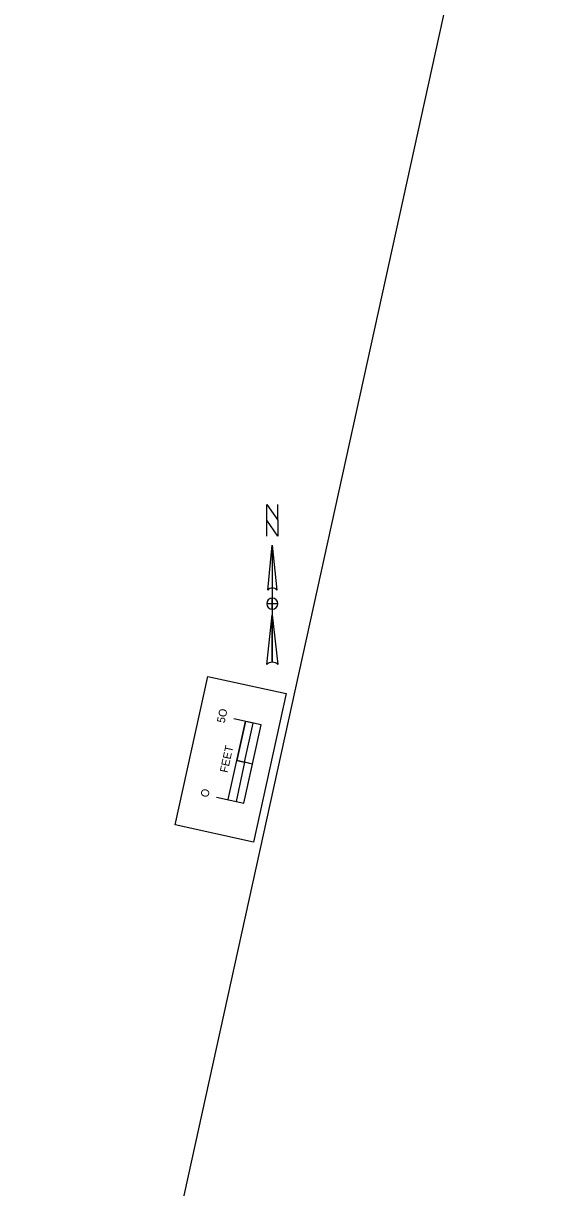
# Model space of a CAD drawing. Extents: x 14104283 to 14120882, y 8635219 to 8671666.
# Drawn here: x 14108486 to 14108813, y 8640168 to 8640895 of the extents above; entities that cross this region are included whole.
import ezdxf

# ---------------------------------------------------------------- set-up
doc = ezdxf.new("R2010")
doc.units = 0
for name, color, linetype in [('dsnCellsNorthArrow', 7, 'Continuous'), ('dsnCellsScaleBlock', 7, 'Continuous'), ('dsnNonPlotable', 7, 'Continuous')]:
    doc.layers.add(name, color=color, linetype=linetype)

msp = doc.modelspace()

# ---------------------------------------------------------------- linework, layer by layer
at = {"layer": 'dsnCellsNorthArrow'}
for p, q in [((14108641.86, 8640569.29), (14108644.67, 8640541.12)), ((14108641.86, 8640569.29), (14108641.86, 8640496.05)), ((14108639.04, 8640541.12), (14108639.04, 8640541.12)), ((14108639.15, 8640541.38), (14108639.67, 8640541.97)), ((14108641.86, 8640529.15), (14108641.86, 8640529.15)), ((14108638.34, 8640494.64), (14108641.86, 8640525.63))]:
    msp.add_line(p, q, dxfattribs=at)
msp.add_lwpolyline([(14108645.38, 8640574.93), (14108638.34, 8640584.79), (14108638.34, 8640594.65), (14108645.38, 8640584.79)], close=True, dxfattribs=at)
for points in [[(14108638.34, 8640574.93), (14108638.34, 8640594.65), (14108645.38, 8640584.79), (14108645.38, 8640594.65)], [(14108639.04, 8640541.12), (14108641.86, 8640569.29), (14108641.86, 8640542.53)], [(14108645.38, 8640532.67), (14108641.86, 8640532.67), (14108641.86, 8640536.19)], [(14108641.86, 8640529.15), (14108641.86, 8640532.67), (14108638.34, 8640532.67)], [(14108641.86, 8640496.05), (14108641.86, 8640525.63), (14108645.38, 8640494.64)]]:
    msp.add_lwpolyline(points, dxfattribs=at)
for centre, radius, start, end in [((14108641.86, 8640532.67), 3.52, 90, 180), ((14108641.86, 8640539.01), 3.52, 90.02039, 143.12574), ((14108641.86, 8640539.01), 3.52, 36.84806, 90.02184), ((14108641.86, 8640532.67), 3.52, 0, 90), ((14108641.86, 8640532.67), 3.52, 180, 270), ((14108641.86, 8640532.67), 3.52, 270, 360), ((14108641.86, 8640490.95), 5.1, 89.98939, 133.61895), ((14108641.86, 8640490.94), 5.11, 46.40206, 90.00064)]:
    msp.add_arc(centre, radius, start, end, dxfattribs=at)
at = {"layer": 'dsnCellsScaleBlock'}
msp.add_line((14108629.49, 8640432.47), (14108619.72, 8640434.62), dxfattribs=at)
msp.add_line((14108629.49, 8640432.47), (14108619.72, 8640434.62), dxfattribs=at)
for points in [[(14108630.04, 8640383.72), (14108581.2, 8640394.45), (14108601.59, 8640487.23), (14108650.42, 8640476.5)], [(14108581.2, 8640394.45), (14108601.59, 8640487.23), (14108650.42, 8640476.5), (14108630.04, 8640383.72)], [(14108630.04, 8640383.72), (14108581.2, 8640394.45), (14108601.59, 8640487.23), (14108650.42, 8640476.5)], [(14108624.57, 8640433.55), (14108629.93, 8640457.97), (14108625.08, 8640459.04), (14108619.72, 8640434.62)], [(14108624.12, 8640408.05), (14108629.49, 8640432.47), (14108624.57, 8640433.55), (14108619.2, 8640409.13)]]:
    msp.add_lwpolyline(points, close=True, dxfattribs=at)
for points in [[(14108607.03, 8640411.81), (14108624.12, 8640408.05), (14108634.85, 8640456.89), (14108617.76, 8640460.64)], [(14108614.35, 8640410.2), (14108625.08, 8640459.04)]]:
    msp.add_lwpolyline(points, dxfattribs=at)
at = {"layer": 'dsnNonPlotable'}
msp.add_lwpolyline([(14107490.45, 8639880.3), (14107826.84, 8641411.28), (14108813.31, 8641194.53), (14108476.92, 8639663.55)], close=True, dxfattribs=at)

# ---------------------------------------------------------------- texts
at = {"layer": 'dsnCellsScaleBlock'}
for s, p in [('5O', (14108612, 8640457.74)), ('FEET', (14108613.88, 8640426.71)), ('O', (14108601.79, 8640411.29))]:
    msp.add_text(s, height=5, rotation=77.60784, dxfattribs=at).set_placement(p)

doc.saveas('drawing.dxf')
